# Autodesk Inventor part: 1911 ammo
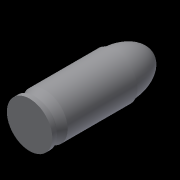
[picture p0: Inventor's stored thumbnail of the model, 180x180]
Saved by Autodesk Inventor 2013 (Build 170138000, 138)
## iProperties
Created: 2013-03
Part Number: 1911 ammo
Material: Generic
Document SubType Name: Modeling
Designer: John
Density: 1 g/cm^3
Author: John
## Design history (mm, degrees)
sketch "Sketch1"
  geometry: L1 (11.595, 10.374)-(11.595, 9.255); L2 (10.679, 11.177)-(10.679, 10.374); L3 (10.679, 11.177)-(11.595, 12.964); L4 (11.595, 29.838)-(11.595, 12.964); L5 (11.275, 29.838)-(11.595, 29.838); L6 (6.095, 9.255)-(11.595, 9.255); L7 (6.095, 9.255)-(6.095, 38.483); L8 (10.679, 10.374)-(11.595, 10.374); 1 further point; 1 other entity
  constraints: 16 end point, 3 perpendicular, 1 horizontal, 4 other
revolve "Revolution1" sketch "Sketch1" stored, may be unused: angle "d24" = 90 deg
body "Solid1"
